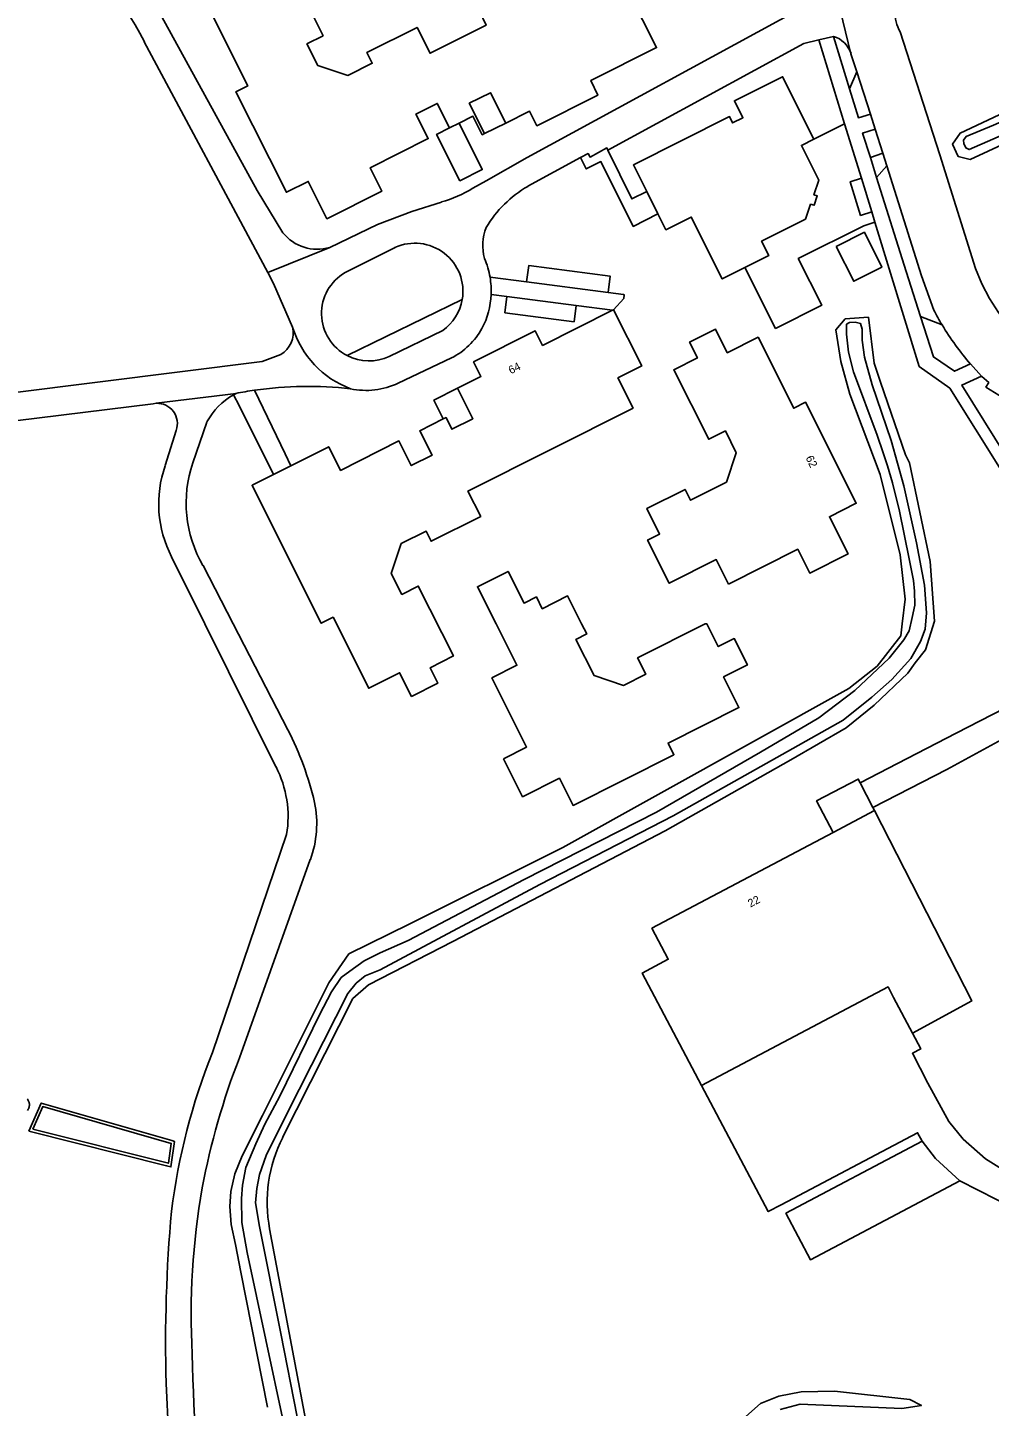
# Model space of a CAD drawing. Extents: x 158132 to 159658, y 385257 to 387209.
# Drawn here: x 158709.3 to 158829.4, y 386402.3 to 386574.5 of the extents above; entities that cross this region are included whole.
import ezdxf

# ---------------------------------------------------------------- set-up
doc = ezdxf.new("R2010")
doc.units = 0
for name, color, linetype in [('IMGEO_Gemengd_bos', 7, 'Continuous'), ('IMGEO_Groenvoorziening', 7, 'Continuous'), ('IMGEO_Pand', 7, 'Continuous'), ('IMGEO_Pand_nummerreeks', 7, 'Continuous'), ('IMGEO_Parkeervlak_open', 7, 'Continuous'), ('IMGEO_Rijbaan_lokaal_gesloten', 7, 'Continuous'), ('IMGEO_Rijbaan_lokaal_open', 7, 'Continuous'), ('IMGEO_Voetpad_open', 7, 'Continuous'), ('IMGEO_Waterloop', 7, 'Continuous')]:
    doc.layers.add(name, color=color, linetype=linetype)

msp = doc.modelspace()

# ---------------------------------------------------------------- linework, layer by layer
at = {"layer": 'IMGEO_Gemengd_bos'}
for points in [[(158741.14, 386435.86), (158749.9, 386453.2), (158751.88, 386454.91), (158762.38, 386460.33), (158788.92, 386474.18), (158804.62, 386483.01), (158811.53, 386487.03), (158815.04, 386489.85), (158819.22, 386493.84), (158820.16, 386495.14), (158821.42, 386496.79), (158822.56, 386500.36), (158822.01, 386507.82), (158819.46, 386520.12), (158818.94, 386521.12), (158815.82, 386530.22), (158815.03, 386532.59), (158814.3, 386538.32), (158811.41, 386538.12), (158810.22, 386536.74), (158810.88, 386532.79), (158812, 386528.71), (158815.76, 386518.66), (158818.29, 386508.65), (158818.92, 386503.11), (158818.54, 386500), (158818.36, 386498.5), (158815.42, 386494.75), (158811.85, 386491.92), (158776.15, 386472.09), (158756.93, 386462.48), (158749.42, 386458.79), (158746.9, 386455.19), (158738.64, 386438.6), (158736.09, 386433.56), (158735.15, 386431.32), (158734.67, 386429.11), (158734.55, 386427.23), (158734.72, 386424.99), (158735.24, 386422.5), (158735.92, 386419.01), (158739.24, 386402.17)], [(158709.27, 386439.23), (158709.32, 386439.31), (158709.37, 386439.39), (158709.42, 386439.48), (158709.45, 386439.57), (158709.48, 386439.66), (158709.5, 386439.75), (158709.51, 386439.85), (158709.51, 386439.95), (158709.51, 386440.04), (158709.49, 386440.14), (158709.47, 386440.23), (158709.44, 386440.32), (158709.4, 386440.41), (158709.36, 386440.49), (158709.3, 386440.58), (158709.24, 386440.65)], [(158709.42, 386436.64), (158726.64, 386432.32), (158727.19, 386432.18), (158727.63, 386435.37), (158727.32, 386435.46), (158710.98, 386440.16), (158709.42, 386436.64)], [(158757.66, 386330.04), (158755.47, 386338), (158744.28, 386399.14), (158739.51, 386424.44)]]:
    msp.add_lwpolyline(points, dxfattribs=at)
msp.add_arc((158757.2, 386427.75), 17.99, 153.1854, 190.5979, dxfattribs=at)
at = {"layer": 'IMGEO_Groenvoorziening'}
msp.add_lwpolyline([(158871.54, 386578.36), (158847.34, 386567.44), (158827.03, 386558.04), (158825.5, 386558.41), (158824.82, 386559.92), (158825.76, 386561.3), (158845.97, 386570.81), (158869.71, 386581.02), (158870.09, 386581.19)], dxfattribs=at)
at = {"layer": 'IMGEO_Pand'}
for points in [[(158742.66, 386580.57), (158741.86, 386582.15), (158738.92, 386580.68), (158737.93, 386582.65), (158734.71, 386581.03), (158736.2, 386578.04), (158732.33, 386576.1), (158736.78, 386567.22), (158735.31, 386566.48), (158741.61, 386553.92), (158744.33, 386555.29), (158746.67, 386550.62), (158753.55, 386554.07), (158752.08, 386557), (158759.32, 386560.63), (158757.79, 386563.7), (158760.45, 386565.03), (158761.99, 386561.96)], [(158742.66, 386580.57), (158746.2, 386573.49), (158744.17, 386572.47), (158745.52, 386569.77), (158749.28, 386568.52), (158752.34, 386570.05), (158751.67, 386571.39), (158757.93, 386574.53), (158759.55, 386571.29), (158766.58, 386574.81), (158765.67, 386576.62), (158773.39, 386580.49), (158774.25, 386578.76), (158780.14, 386581.71)], [(158769.03, 386562.57), (158771.99, 386564.05), (158772.9, 386562.24), (158780.53, 386566.07), (158779.62, 386567.87), (158787.86, 386572), (158784.36, 386578.96), (158782.09, 386577.82), (158780.14, 386581.71)], [(158786.62, 386554.02), (158784.95, 386557.35), (158796.96, 386563.38), (158797.35, 386562.6), (158798.63, 386563.24), (158797.57, 386565.35), (158803.58, 386568.36), (158807.5, 386560.55)], [(158766.35, 386561.26), (158764.46, 386565.04), (158767.12, 386566.37), (158769.03, 386562.57)], [(158763.18, 386562.56), (158764.91, 386563.43), (158766.08, 386561.12), (158766.35, 386561.26)], [(158761.99, 386561.96), (158760.38, 386561.16), (158763.28, 386555.36), (158766.08, 386556.77), (158763.18, 386562.56)], [(158761.99, 386561.96), (158763.18, 386562.56)], [(158807.5, 386560.55), (158805.94, 386559.78), (158808.12, 386555.45), (158807.51, 386553.62), (158807.91, 386553.48), (158807.52, 386552.3), (158807.09, 386552.44), (158806.47, 386550.57), (158800.96, 386547.81), (158801.86, 386546.02), (158798.89, 386544.53)], [(158788.02, 386551.22), (158786.62, 386554.02)], [(158788.02, 386551.22), (158789.02, 386549.24), (158792.17, 386550.82), (158796.05, 386543.1), (158798.89, 386544.53)], [(158810.3, 386547.17), (158813.8, 386548.93), (158815.99, 386544.58), (158812.48, 386542.82), (158810.3, 386547.17)], [(158782.47, 386539.25), (158785.99, 386532.23), (158783.01, 386530.74), (158784.91, 386526.96), (158764.29, 386516.61), (158765.88, 386513.43), (158759.69, 386510.33), (158759.05, 386511.6), (158755.94, 386510.04), (158754.71, 386506.32), (158756.03, 386503.69), (158758.09, 386504.73), (158762.48, 386496), (158759.57, 386494.54), (158760.54, 386492.61), (158757.24, 386490.95), (158755.75, 386493.91), (158751.9, 386491.97), (158747.44, 386500.84), (158745.97, 386500.1), (158739.64, 386512.72), (158737.33, 386517.32), (158740.02, 386518.67)], [(158762.99, 386529.46), (158765.91, 386530.92), (158765, 386532.74), (158772.7, 386536.6), (158773.61, 386534.8), (158782.36, 386539.2)], [(158782.36, 386539.2), (158782.47, 386539.25)], [(158796.84, 386504.99), (158805.49, 386509.34), (158806.98, 386506.36), (158811.76, 386508.76), (158809.43, 386513.39), (158812.79, 386515.08), (158806.46, 386527.69), (158804.99, 386526.95), (158800.53, 386535.82), (158796.68, 386533.89), (158795.2, 386536.83), (158791.97, 386535.21), (158792.96, 386533.24), (158790, 386531.75), (158794.36, 386523.07), (158796.44, 386524.12), (158797.81, 386521.39), (158796.59, 386517.72), (158792.09, 386515.46), (158791.41, 386516.81), (158786.63, 386514.41), (158788.23, 386511.22), (158786.73, 386510.47), (158789.43, 386505.09), (158795.31, 386508.04), (158796.84, 386504.99)], [(158762.99, 386529.46), (158764.9, 386525.64), (158762.28, 386524.32), (158761.55, 386525.78), (158761.21, 386525.61)], [(158742.18, 386519.76), (158746.9, 386522.13), (158748.37, 386519.19), (158755.67, 386522.86), (158757.21, 386519.78), (158759.8, 386521.07), (158758.27, 386524.13), (158761.21, 386525.61)], [(158740.02, 386518.67), (158742.18, 386519.76)], [(158768.72, 386483.16), (158771.62, 386484.62), (158767.28, 386493.27), (158770.4, 386494.84), (158767.81, 386500), (158765.48, 386504.64), (158769.31, 386506.56), (158771.3, 386502.6), (158772.84, 386503.37), (158773.57, 386501.91), (158776.73, 386503.5), (158778.49, 386500), (158779.12, 386498.75), (158777.77, 386498.07), (158780.04, 386493.55), (158783.72, 386492.33), (158786.49, 386493.72), (158785.47, 386495.75), (158793.93, 386500), (158794.14, 386500), (158795.56, 386497.18), (158797.55, 386498.18), (158799.19, 386494.89), (158796.21, 386493.39), (158798.13, 386489.56), (158789.28, 386485.12), (158790.01, 386483.66), (158777.42, 386477.34), (158775.72, 386480.72), (158771.11, 386478.41), (158768.72, 386483.16)], [(158813.28, 386480.17), (158813.04, 386480.63), (158807.84, 386477.9), (158809.92, 386473.95)], [(158813.28, 386480.17), (158814.87, 386477.09)], [(158815.08, 386476.68), (158814.87, 386477.09)], [(158809.92, 386473.95), (158815.08, 386476.68)], [(158819.8, 386448.9), (158827.22, 386452.91), (158815.08, 386476.68)], [(158793.47, 386442.36), (158786.06, 386456.4), (158789.31, 386458.12), (158787.27, 386461.99), (158809.92, 386473.95)], [(158819.8, 386448.9), (158817.46, 386453.34), (158816.76, 386454.66), (158793.47, 386442.36)]]:
    msp.add_lwpolyline(points, dxfattribs=at)
at = {"layer": 'IMGEO_Parkeervlak_open'}
for points in [[(158812.86, 386568.96), (158811.96, 386566.83)], [(158815.34, 386555.79), (158816.6, 386557.24)], [(158820.83, 386538.4), (158823.51, 386537.36)]]:
    msp.add_lwpolyline(points, dxfattribs=at)
at = {"layer": 'IMGEO_Rijbaan_lokaal_gesloten'}
for points in [[(158808.97, 386584.02), (158809.09, 386583.79), (158812.13, 386571.24)], [(158806.1, 386577), (158771.7, 386558.28), (158766.58, 386555.35), (158764.89, 386554.44)], [(158741.17, 386548.87), (158737.97, 386554.13), (158726.07, 386575.86)], [(158833.53, 386535.48), (158831.85, 386537.27), (158830.56, 386538.9), (158829.43, 386540.64), (158828.46, 386542.48), (158827.67, 386544.4), (158823.22, 386558.59), (158818.27, 386573.98)], [(158723.86, 386572.73), (158739.28, 386543.92)], [(158781.78, 386559.2), (158806.24, 386572.52), (158808.12, 386572.96)], [(158808.12, 386572.96), (158809.95, 386573.4)], [(158812.13, 386571.24), (158812.86, 386568.96)], [(158812.86, 386568.96), (158814.56, 386563.68)], [(158814.56, 386563.68), (158815.14, 386561.83)], [(158815.14, 386561.83), (158816.1, 386558.8)], [(158406.58, 386559.5), (158407.36, 386554.43), (158412.58, 386546.23), (158416.91, 386541.17), (158442.58, 386509.71), (158448.36, 386503.02), (158452.61, 386500), (158453.96, 386499.04), (158456.49, 386498.14), (158462.82, 386498.14), (158466.25, 386498.5), (158477.43, 386500), (158500, 386502.83), (158738.6, 386532.78), (158740.9, 386533.67)], [(158771.76, 386554.67), (158778.36, 386558.26)], [(158778.36, 386558.26), (158779.3, 386558.77), (158779.55, 386558.32), (158781.64, 386559.47), (158781.78, 386559.2)], [(158816.1, 386558.8), (158816.6, 386557.24)], [(158816.6, 386557.24), (158820.95, 386543.47), (158822.48, 386539.21)], [(158760.97, 386552.71), (158757.28, 386551.54), (158753, 386549.89), (158747.02, 386547.04)], [(158739.28, 386543.92), (158747.02, 386547.04)], [(158755.18, 386547.03), (158748.96, 386543.92)], [(158739.28, 386543.92), (158740.02, 386542.53), (158742.38, 386537.07)], [(158761.14, 386536.67), (158754.45, 386533.43)], [(158755.58, 386530.07), (158762.25, 386533.23)], [(158827.06, 386532.48), (158828.44, 386530.95)], [(158828.44, 386530.95), (158828.49, 386530.9), (158829.34, 386530.16), (158828.99, 386529.6), (158831.15, 386528.26)], [(158735.32, 386528.8), (158725.35, 386527.57)], [(158725.35, 386527.57), (158724.95, 386527.52), (158601.22, 386512.28), (158504.01, 386500), (158500, 386499.49), (158489.2, 386498.32), (158473.3, 386495.97), (158467.81, 386495.38), (158464.4, 386494.85)], [(158727.85, 386524.18), (158726.47, 386519.78)], [(158729.91, 386520.12), (158731.69, 386525.23)], [(158727.27, 386508.38), (158731.44, 386500), (158740.31, 386482.15)], [(158741.8, 386486.78), (158734.97, 386500), (158731.2, 386507.29)], [(158741.64, 386473.71), (158732.37, 386446.49)], [(158735.74, 386445.81), (158744.6, 386470.56)]]:
    msp.add_lwpolyline(points, dxfattribs=at)
for centre, radius, start, end in [((158698.6, 386560.29), 28.16, 26.2071, 64.993), ((158823.46, 386576.71), 5.87, 181.7935, 207.7556), ((158808.95, 386570.21), 3.35, 18.006, 72.6012), ((158778.94, 386542.25), 14.34, 120.0335, 149.5563), ((158756.69, 386567.75), 15.63, 285.8673, 301.6121), ((158772.17, 386547.28), 6.03, 158.2096, 195.5558), ((158745.47, 386552.33), 5.52, 218.8685, 286.3263), ((158757.65, 386541.56), 6.01, 350.1419, 114.3135), ((158756.88, 386541.6), 10.31, 9.5433, 23.2252), ((158751.92, 386538.78), 5.92, 119.9682, 242.6555), ((158756.74, 386541.61), 10.45, 357.5576, 9.3385), ((158756.97, 386541.63), 10.23, 332.454, 357.4245), ((158757.65, 386541.56), 6.01, 305.5764, 350.1196), ((158853.62, 386555.4), 35.1, 207.4759, 210.9232), ((158853.03, 386555.07), 34.42, 210.9668, 221.0308), ((158739.3, 386536.39), 3.16, 300.4736, 12.3826), ((158753.89, 386540.66), 12.06, 197.3288, 249.2482), ((158757.95, 386541.44), 9.27, 297.6407, 330.6688), ((158751.92, 386538.78), 5.92, 242.6499, 295.3441), ((158739.67, 386520.36), 9.5, 117.2405, 119.3159), ((158744.36, 386481.58), 48.09, 98.0568, 100.8437), ((158744.41, 386481.28), 48.39, 83.8147, 98.0574), ((158751.56, 386538.7), 9.52, 258.2375, 294.9432), ((158725.46, 386525.04), 2.53, 340.3234, 92.5607), ((158739.17, 386521.26), 8.47, 119.3824, 152.0297), ((158744.79, 386515.13), 15.7, 161.4739, 209.9818), ((158740.06, 386515), 14.4, 160.6366, 207.4017), ((158705.49, 386468.33), 40.74, 13.323, 26.9362), ((158728.12, 386475.91), 13.7, 350.7437, 27.0781), ((158732.27, 386475.07), 13.13, 339.9077, 11.5977), ((158806.54, 386416.79), 79.89, 158.1763, 172.9044), ((158821.96, 386412.32), 92.49, 158.7717, 169.2508), ((158822.47, 386413.68), 92.75, 170.1343, 183.0174), ((158914.06, 386410.09), 187.54, 174.9315, 181.5121), ((158993.77, 386414.07), 263.97, 181.1448, 186.5873), ((159028.95, 386416.44), 302.57, 182.1399, 187.5181)]:
    msp.add_arc(centre, radius, start, end, dxfattribs=at)
at = {"layer": 'IMGEO_Rijbaan_lokaal_open'}
for points in [[(158814.57, 386558.26), (158813.59, 386561.33), (158815.14, 386561.83)], [(158816.1, 386558.8), (158814.57, 386558.26)], [(158749.2, 386533.52), (158763.57, 386540.53)], [(158839.41, 386431.05), (158836.12, 386429.94), (158833.25, 386430.8), (158830.92, 386431.92), (158828.94, 386433.18), (158826.15, 386435.66), (158824.34, 386437.85), (158821.72, 386442.65), (158819.81, 386446.38), (158820.85, 386446.91), (158819.8, 386448.9)], [(158793.47, 386442.36), (158801.79, 386426.59), (158803.43, 386427.46), (158820.46, 386436.45), (158821.03, 386435.38)], [(158825.73, 386430.42), (158822.71, 386433.23), (158821.03, 386435.38)], [(158825.73, 386430.42), (158834.9, 386425.77), (158838.25, 386423.8)]]:
    msp.add_lwpolyline(points, dxfattribs=at)
at = {"layer": 'IMGEO_Voetpad_open'}
for points in [[(158811.34, 386562.48), (158808.12, 386572.96)], [(158809.95, 386573.4), (158811.96, 386566.83)], [(158811.96, 386566.83), (158813.07, 386563.23), (158814.56, 386563.68)], [(158769.03, 386562.57), (158766.35, 386561.26)], [(158807.5, 386560.55), (158811.34, 386562.48)], [(158813.43, 386555.67), (158811.34, 386562.48)], [(158778.36, 386558.26), (158779.06, 386556.85), (158780.9, 386557.76), (158784.94, 386549.67), (158788.02, 386551.22)], [(158781.78, 386559.2), (158784.77, 386553.1), (158786.62, 386554.02)], [(158814.57, 386558.26), (158815.34, 386555.79)], [(158814.72, 386551.47), (158813.33, 386551.04), (158812.04, 386555.24), (158813.43, 386555.67)], [(158814.72, 386551.47), (158813.43, 386555.67)], [(158820.83, 386538.4), (158819.01, 386544.03), (158815.34, 386555.79)], [(158815.11, 386550.18), (158814.72, 386551.47)], [(158798.89, 386544.53), (158802.72, 386536.92), (158808.48, 386539.81), (158805.55, 386545.65), (158813.72, 386549.75), (158815.11, 386550.18)], [(158815.11, 386550.18), (158820.64, 386532.18), (158824.46, 386529.47), (158830.89, 386519.21)], [(158781.81, 386541.39), (158782.07, 386543.43), (158771.89, 386544.76), (158771.62, 386542.72)], [(158771.62, 386542.72), (158767.05, 386543.31)], [(158781.81, 386541.39), (158771.62, 386542.72)], [(158769.16, 386540.91), (158767.18, 386541.17)], [(158777.81, 386539.79), (158777.55, 386537.76), (158768.9, 386538.88), (158769.16, 386540.91)], [(158769.16, 386540.91), (158777.81, 386539.79)], [(158782.47, 386539.25), (158783.74, 386540.66), (158783.8, 386541.13), (158783.7, 386541.15), (158781.81, 386541.39)], [(158782.36, 386539.2), (158777.81, 386539.79)], [(158827.06, 386532.48), (158825.08, 386531.56), (158822.45, 386533.36), (158820.83, 386538.4)], [(158831.48, 386520.99), (158825.96, 386529.85), (158828.44, 386530.95)], [(158737.62, 386529.19), (158741.45, 386521.27), (158742.18, 386519.76)], [(158761.21, 386525.61), (158760.03, 386527.97), (158762.99, 386529.46)], [(158735.01, 386528.64), (158735.69, 386527.3), (158740.02, 386518.67)], [(158832.79, 386490.22), (158825.29, 386486.36), (158817.96, 386482.58), (158813.28, 386480.17)], [(158814.87, 386477.09), (158824.09, 386481.84), (158833.28, 386486.8)], [(158821.03, 386435.38), (158804, 386426.39), (158807.07, 386420.58), (158825.73, 386430.42)]]:
    msp.add_lwpolyline(points, dxfattribs=at)
at = {"layer": 'IMGEO_Waterloop'}
for points in [[(158871.12, 386579.19), (158846.53, 386567.85), (158826.88, 386559.26), (158826.46, 386559.47), (158826.22, 386560.01), (158826.18, 386560.43), (158826.51, 386560.91), (158829.95, 386562.3), (158850.3, 386571.19), (158870.4, 386580.59)], [(158743.56, 386389.35), (158736.69, 386421.47), (158736.05, 386425.22), (158736.02, 386428.24), (158736.13, 386429.9), (158736.54, 386432.1), (158737.79, 386435.07), (158738.91, 386437.52), (158740.8, 386441.03), (158745.74, 386451.17), (158747.24, 386454.05), (158748.45, 386455.82), (158749.55, 386456.64), (158751.33, 386457.92), (158753.31, 386458.94), (158756.8, 386460.48), (158771.33, 386468.08), (158787.82, 386476.5), (158800.84, 386483.97), (158808.13, 386488.29), (158812.62, 386491.7), (158816.9, 386495.73), (158818.73, 386498.01), (158819.41, 386499.14), (158819.77, 386500.81), (158820.1, 386502.35), (158820.08, 386504.08), (158819.94, 386505.43), (158819.39, 386508.12), (158818.21, 386514.11), (158817.3, 386517.65), (158816.69, 386519.77), (158816.17, 386521.36), (158815.39, 386523.59), (158812.46, 386531.51), (158811.84, 386533.94), (158811.59, 386536.21), (158811.58, 386537.44), (158811.94, 386537.66), (158812.66, 386537.7), (158813.33, 386537.52), (158813.55, 386536.83), (158813.55, 386535.47), (158813.82, 386533.31), (158814.77, 386529.88), (158817.14, 386522.91), (158818.75, 386517.24), (158820.32, 386510.13), (158821.31, 386504.83), (158821.56, 386501.4), (158821.39, 386499.37), (158820.83, 386497.83), (158819.61, 386495.68), (158817.23, 386493.06), (158814.75, 386490.85), (158811.16, 386487.98), (158789.94, 386476.05), (158773.27, 386467.46), (158753.32, 386456.79), (158751.45, 386456.04), (158750.31, 386455.11), (158749.3, 386453.83), (158741.69, 386438.9), (158739.08, 386433.62), (158738.24, 386431.21), (158737.93, 386429.5), (158737.75, 386427.7), (158738.25, 386424.73), (158740.93, 386411.36), (158742.95, 386400.97)], [(158709.93, 386436.89), (158711.18, 386439.72), (158727.22, 386435.11), (158726.88, 386432.64), (158709.93, 386436.89)], [(158803.3, 386401.87), (158805.78, 386402.55), (158818.48, 386402.01), (158820.92, 386402.37), (158819.47, 386403.14), (158810.08, 386404.18), (158805.92, 386404.09), (158803.12, 386403.54), (158800.81, 386402.64), (158799.01, 386401.01)]]:
    msp.add_lwpolyline(points, dxfattribs=at)

# ---------------------------------------------------------------- texts
at = {"layer": 'IMGEO_Pand_nummerreeks'}
for s, rotation, p in [('64', 26.5795, (158769.65, 386531.18)), ('62', 296.1022, (158806.44, 386520.75)), ('22', 27.6796, (158799.57, 386464.57))]:
    msp.add_text(s, height=1, rotation=rotation, dxfattribs=at).set_placement(p)

doc.saveas('drawing.dxf')
